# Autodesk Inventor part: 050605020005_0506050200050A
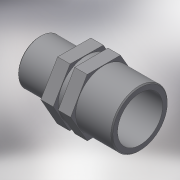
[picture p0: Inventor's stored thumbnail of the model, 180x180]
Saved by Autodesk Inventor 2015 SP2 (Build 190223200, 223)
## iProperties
Created: 2017-05
Part Number: 050605020005_0506050200050A
Material: Generic
Description: PLASSON REDUCING NIPPLE 2"-1/2"
Document SubType Name: Modeling
Designer: KIM
Density: 1 g/cm^3
Appearance: Default
Author: KIM
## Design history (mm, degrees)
derived "050605.ipt"
feature "Solid1::050605.ipt"
tag "TaggingFeature1"
body "Solid1"
other parameters: "d0" = 58, "d1" = 59.614, "d5" = 25, "d6" = 5.8, "d8" = 0.58, "d12" = 0, "d14" = 20.955, "d15" = 16.764, "d16" = 47.6912, "d17" = 16, "d18" = 2.9, "d19" = 63, "d21" = 0, "H_" = 58, "R_" = 59.614, "E_" = 63, "l_" = 25, "R_1" = 20.955, "l_1" = 16
